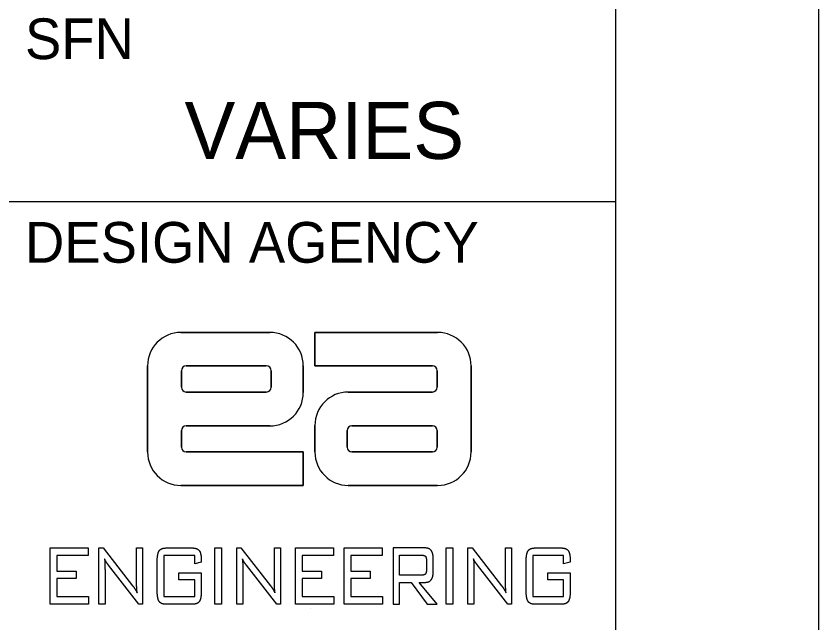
# Model space of a CAD drawing. Extents: x 0 to 34, y -10.4 to 22.
# Drawn here: x 32.028 to 34, y 3.965 to 5.456 of the extents above; entities that cross this region are included whole.
import ezdxf

# ---------------------------------------------------------------- set-up
doc = ezdxf.new("R2010")
doc.units = 0
for name, color, linetype in [('SH_Border', 7, 'Continuous'), ('SH_Cut_Line', 7, 'Continuous'), ('SH_Data', 7, 'Continuous'), ('TX_X_20', 7, 'Continuous')]:
    doc.layers.add(name, color=color, linetype=linetype)

msp = doc.modelspace()

# ---------------------------------------------------------------- linework, layer by layer
at = {"layer": 'SH_Border'}
msp.add_line((32, 5), (33.5, 5), dxfattribs=at)
msp.add_lwpolyline([(1.5, 21.5), (33.5, 21.5), (33.5, 0.5), (1.5, 0.5)], close=True, dxfattribs=at)
at = {"layer": 'SH_Cut_Line'}
msp.add_lwpolyline([(0, 0), (34, 0), (34, 22), (0, 22)], close=True, dxfattribs=at)
at = {"layer": 'SH_Data'}
msp.add_line((32.75, 4), (32.75, 4), dxfattribs=at)
at = {"layer": 'TX_X_20'}
for p, q in [((32.6515, 4.6788), (32.433, 4.6788)), ((32.433, 4.6788), (32.6515, 4.6788)), ((32.762, 4.6788), (33.0635, 4.6788)), ((32.762, 4.5967), (32.762, 4.6788)), ((32.351, 4.5967), (32.351, 4.3852)), ((32.351, 4.3852), (32.351, 4.5967)), ((32.4459, 4.5967), (32.6426, 4.5967)), ((32.6426, 4.5967), (32.4459, 4.5967)), ((32.7336, 4.5315), (32.7336, 4.5967)), ((32.7336, 4.5967), (32.7336, 4.5315)), ((33.0507, 4.5967), (32.762, 4.5967)), ((33.1456, 4.3852), (33.1456, 4.5967)), ((33.1456, 4.5967), (33.1456, 4.3852)), ((32.434, 4.5444), (32.434, 4.5849)), ((32.434, 4.5849), (32.434, 4.5444)), ((32.6545, 4.5849), (32.6545, 4.5444)), ((32.6545, 4.5444), (32.6545, 4.5849)), ((33.0626, 4.5849), (33.0626, 4.5444)), ((33.0626, 4.5444), (33.0626, 4.5849)), ((32.6426, 4.5325), (32.4459, 4.5325)), ((32.4459, 4.5325), (32.6426, 4.5325)), ((33.0507, 4.5325), (32.8441, 4.5325)), ((32.8441, 4.5325), (33.0507, 4.5325)), ((32.434, 4.3971), (32.434, 4.4376)), ((32.434, 4.4376), (32.434, 4.3971)), ((32.4459, 4.4494), (32.6515, 4.4494)), ((32.6515, 4.4494), (32.4459, 4.4494)), ((32.762, 4.4504), (32.762, 4.3852)), ((32.762, 4.3852), (32.762, 4.4504)), ((32.8411, 4.3971), (32.8411, 4.4376)), ((32.8411, 4.4376), (32.8411, 4.3971)), ((32.853, 4.4494), (33.0507, 4.4494)), ((33.0507, 4.4494), (32.853, 4.4494)), ((33.0626, 4.4376), (33.0626, 4.3971)), ((33.0626, 4.3971), (33.0626, 4.4376)), ((32.4459, 4.3852), (32.7336, 4.3852)), ((32.7336, 4.3852), (32.7336, 4.3031)), ((33.0507, 4.3852), (32.853, 4.3852)), ((32.853, 4.3852), (33.0507, 4.3852)), ((32.7336, 4.3031), (32.433, 4.3031)), ((32.8441, 4.3031), (33.0635, 4.3031)), ((33.0635, 4.3031), (32.8441, 4.3031)), ((32.3975, 4.1495), (32.4602, 4.1495)), ((33.3037, 4.1495), (33.3663, 4.1495)), ((33.0526, 4.0917), (33.0526, 4.1227)), ((32.3748, 4.0439), (32.3748, 4.1168)), ((33.0361, 4.1173), (33.0361, 4.0971)), ((33.2809, 4.0439), (33.2809, 4.1168)), ((32.4602, 4.0111), (32.3975, 4.0111)), ((33.3663, 4.0111), (33.3037, 4.0111))]:
    msp.add_line(p, q, dxfattribs=at)
for points in [[(33.0635, 4.6788), (32.762, 4.6788), (32.762, 4.5967), (33.0507, 4.5967)], [(32.433, 4.3031), (32.7336, 4.3031), (32.7336, 4.3852), (32.4459, 4.3852)], [(32.2465, 4.0927), (32.2465, 4.0111), (32.2317, 4.0111), (32.2317, 4.1495), (32.2419, 4.1495), (32.3144, 4.0569)], [(32.3239, 4.0736), (32.3239, 4.1495), (32.3387, 4.1495), (32.3387, 4.0111), (32.3297, 4.0111), (32.2553, 4.1074)], [(32.5851, 4.0927), (32.5851, 4.0111), (32.5703, 4.0111), (32.5703, 4.1495), (32.5804, 4.1495), (32.6529, 4.0569)], [(32.6625, 4.0736), (32.6625, 4.1495), (32.6773, 4.1495), (32.6773, 4.0111), (32.6682, 4.0111), (32.5938, 4.1074)], [(33.032, 4.1495), (32.954, 4.1495), (32.954, 4.0111), (32.9702, 4.0111), (32.9702, 4.065), (32.9987, 4.065), (33.0381, 4.0111), (33.0621, 4.0111), (33.0178, 4.065), (33.032, 4.065)], [(33.1527, 4.0927), (33.1527, 4.0111), (33.1379, 4.0111), (33.1379, 4.1495), (33.148, 4.1495), (33.2205, 4.0569)], [(33.2301, 4.0736), (33.2301, 4.1495), (33.2449, 4.1495), (33.2449, 4.0111), (33.2358, 4.0111), (33.1614, 4.1074)], [(32.483, 4.1183), (32.483, 4.1149), (32.4668, 4.1103), (32.4668, 4.1307), (32.3909, 4.1307), (32.3909, 4.0304), (32.4668, 4.0304), (32.4668, 4.071), (32.4276, 4.071), (32.4276, 4.0886), (32.483, 4.0886), (32.483, 4.0439)], [(33.0257, 4.0829), (32.9702, 4.0829), (32.9702, 4.1316), (33.0257, 4.1316)], [(33.3891, 4.1183), (33.3891, 4.1149), (33.3729, 4.1103), (33.3729, 4.1307), (33.2971, 4.1307), (33.2971, 4.0304), (33.3729, 4.0304), (33.3729, 4.071), (33.3338, 4.071), (33.3338, 4.0886), (33.3891, 4.0886), (33.3891, 4.0439)]]:
    msp.add_lwpolyline(points, dxfattribs=at)
for points in [[(32.1121, 4.0111), (32.1121, 4.1495), (32.2053, 4.1495), (32.2053, 4.131), (32.1283, 4.131), (32.1283, 4.0925), (32.1754, 4.0925), (32.1754, 4.0742), (32.1283, 4.0742), (32.1283, 4.0301), (32.2061, 4.0301), (32.2061, 4.0111)], [(32.5166, 4.0111), (32.5166, 4.1495), (32.5329, 4.1495), (32.5329, 4.0111)], [(32.7147, 4.0111), (32.7147, 4.1495), (32.8079, 4.1495), (32.8079, 4.131), (32.7309, 4.131), (32.7309, 4.0925), (32.778, 4.0925), (32.778, 4.0742), (32.7309, 4.0742), (32.7309, 4.0301), (32.8087, 4.0301), (32.8087, 4.0111)], [(32.8343, 4.0111), (32.8343, 4.1495), (32.9276, 4.1495), (32.9276, 4.131), (32.8506, 4.131), (32.8506, 4.0925), (32.8977, 4.0925), (32.8977, 4.0742), (32.8506, 4.0742), (32.8506, 4.0301), (32.9283, 4.0301), (32.9283, 4.0111)], [(33.0842, 4.0111), (33.0842, 4.1495), (33.1005, 4.1495), (33.1005, 4.0111)]]:
    msp.add_lwpolyline(points, close=True, dxfattribs=at)
for centre, radius, start, end in [((32.433, 4.5967), 0.0821, 90, 180), ((32.433, 4.5967), 0.0821, 90, 180), ((32.6515, 4.5967), 0.0821, 0, 90), ((32.6515, 4.5967), 0.0821, 0, 90), ((33.0635, 4.5967), 0.0821, 0, 90), ((33.0635, 4.5967), 0.0821, 0, 90), ((32.4459, 4.5849), 0.0119, 90, 180), ((32.4459, 4.5849), 0.0119, 90, 180), ((32.6426, 4.5849), 0.0119, 0, 90), ((32.6426, 4.5849), 0.0119, 0, 90), ((33.0507, 4.5849), 0.0119, 0, 90), ((33.0507, 4.5849), 0.0119, 0, 90), ((32.4459, 4.5444), 0.0119, 180, 270), ((32.4459, 4.5444), 0.0119, 180, 270), ((32.6426, 4.5444), 0.0119, 270, 0), ((32.6426, 4.5444), 0.0119, 270, 0), ((33.0507, 4.5444), 0.0119, 270, 0), ((33.0507, 4.5444), 0.0119, 270, 0), ((32.6515, 4.5315), 0.0821, 270, 360), ((32.6515, 4.5315), 0.0821, 270, 360), ((32.8441, 4.4504), 0.0821, 90, 180), ((32.8441, 4.4504), 0.0821, 90, 180), ((32.4459, 4.4376), 0.0119, 90, 180), ((32.4459, 4.4376), 0.0119, 90, 180), ((32.853, 4.4376), 0.0119, 90, 180), ((32.853, 4.4376), 0.0119, 90, 180), ((33.0507, 4.4376), 0.0119, 0, 90), ((33.0507, 4.4376), 0.0119, 0, 90), ((32.433, 4.3852), 0.0821, 180, 270), ((32.433, 4.3852), 0.0821, 180, 270), ((32.4459, 4.3971), 0.0119, 180, 270), ((32.4459, 4.3971), 0.0119, 180, 270), ((32.8441, 4.3852), 0.0821, 180, 270), ((32.8441, 4.3852), 0.0821, 180, 270), ((32.853, 4.3971), 0.0119, 180, 270), ((32.853, 4.3971), 0.0119, 180, 270), ((33.0507, 4.3971), 0.0119, 270, 0), ((33.0507, 4.3971), 0.0119, 270, 0), ((33.0635, 4.3852), 0.0821, 270, 360), ((33.0635, 4.3852), 0.0821, 270, 360)]:
    msp.add_arc(centre, radius, start, end, dxfattribs=at)
for points in [[(32.3748, 4.1168), (32.3748, 4.1356), (32.3795, 4.1426)], [(32.3795, 4.1426), (32.3842, 4.1495), (32.3975, 4.1495)], [(32.4602, 4.1495), (32.4732, 4.1495), (32.4781, 4.1428)], [(32.4781, 4.1428), (32.483, 4.136), (32.483, 4.1183)], [(33.0477, 4.1432), (33.0429, 4.1495), (33.032, 4.1495)], [(33.0526, 4.1227), (33.0526, 4.1368), (33.0477, 4.1432)], [(33.2809, 4.1168), (33.2809, 4.1356), (33.2857, 4.1426)], [(33.2857, 4.1426), (33.2904, 4.1495), (33.3037, 4.1495)], [(33.3663, 4.1495), (33.3794, 4.1495), (33.3842, 4.1428)], [(33.3842, 4.1428), (33.3891, 4.136), (33.3891, 4.1183)], [(32.2536, 4.1094), (32.2481, 4.1165), (32.2454, 4.1229)], [(32.2454, 4.1229), (32.246, 4.1166), (32.2463, 4.1095)], [(32.5921, 4.1094), (32.5866, 4.1165), (32.584, 4.1229)], [(32.584, 4.1229), (32.5845, 4.1166), (32.5848, 4.1095)], [(33.0257, 4.1316), (33.0316, 4.1316), (33.0339, 4.1284)], [(33.0339, 4.1284), (33.0361, 4.1252), (33.0361, 4.1173)], [(33.1597, 4.1094), (33.1542, 4.1165), (33.1516, 4.1229)], [(33.1516, 4.1229), (33.1521, 4.1166), (33.1524, 4.1095)], [(32.2463, 4.1095), (32.2465, 4.1024), (32.2465, 4.0927)], [(32.2553, 4.1074), (32.2547, 4.108), (32.2536, 4.1094)], [(32.5848, 4.1095), (32.5851, 4.1024), (32.5851, 4.0927)], [(32.5938, 4.1074), (32.5932, 4.108), (32.5921, 4.1094)], [(33.1524, 4.1095), (33.1527, 4.1024), (33.1527, 4.0927)], [(33.1614, 4.1074), (33.1608, 4.108), (33.1597, 4.1094)], [(33.0339, 4.0861), (33.0317, 4.0829), (33.0257, 4.0829)], [(33.0361, 4.0971), (33.0361, 4.0892), (33.0339, 4.0861)], [(33.0477, 4.0714), (33.0526, 4.0777), (33.0526, 4.0917)], [(32.3243, 4.0535), (32.3239, 4.0607), (32.3239, 4.0736)], [(32.6628, 4.0535), (32.6625, 4.0607), (32.6625, 4.0736)], [(33.032, 4.065), (33.0429, 4.065), (33.0477, 4.0714)], [(33.2304, 4.0535), (33.2301, 4.0607), (33.2301, 4.0736)], [(32.3144, 4.0569), (32.3169, 4.0538), (32.3197, 4.0493)], [(32.3197, 4.0493), (32.3225, 4.0449), (32.3254, 4.0395)], [(32.3254, 4.0395), (32.3247, 4.0462), (32.3243, 4.0535)], [(32.3795, 4.0181), (32.3748, 4.025), (32.3748, 4.0439)], [(32.483, 4.0439), (32.483, 4.0249), (32.4782, 4.018)], [(32.6529, 4.0569), (32.6554, 4.0538), (32.6582, 4.0493)], [(32.6582, 4.0493), (32.661, 4.0449), (32.6639, 4.0395)], [(32.6639, 4.0395), (32.6632, 4.0462), (32.6628, 4.0535)], [(33.2205, 4.0569), (33.223, 4.0538), (33.2258, 4.0493)], [(33.2258, 4.0493), (33.2286, 4.0449), (33.2315, 4.0395)], [(33.2315, 4.0395), (33.2308, 4.0462), (33.2304, 4.0535)], [(33.2857, 4.0181), (33.2809, 4.025), (33.2809, 4.0439)], [(33.3891, 4.0439), (33.3891, 4.0249), (33.3843, 4.018)], [(32.3975, 4.0111), (32.3842, 4.0111), (32.3795, 4.0181)], [(32.4782, 4.018), (32.4734, 4.0111), (32.4602, 4.0111)], [(33.3037, 4.0111), (33.2904, 4.0111), (33.2857, 4.0181)], [(33.3843, 4.018), (33.3795, 4.0111), (33.3663, 4.0111)]]:
    msp.add_open_spline(points, degree=2, dxfattribs=at)

# ---------------------------------------------------------------- texts
at = {"layer": 'SH_Data'}
for s, height, p in [('SFN', 0.1, (32.05, 5.35)), ('VARIES', 0.14, (32.4417, 5.105)), ('DESIGN AGENCY', 0.1, (32.05, 4.85))]:
    msp.add_text(s, height=height, dxfattribs=at).set_placement(p)

doc.saveas('drawing.dxf')
